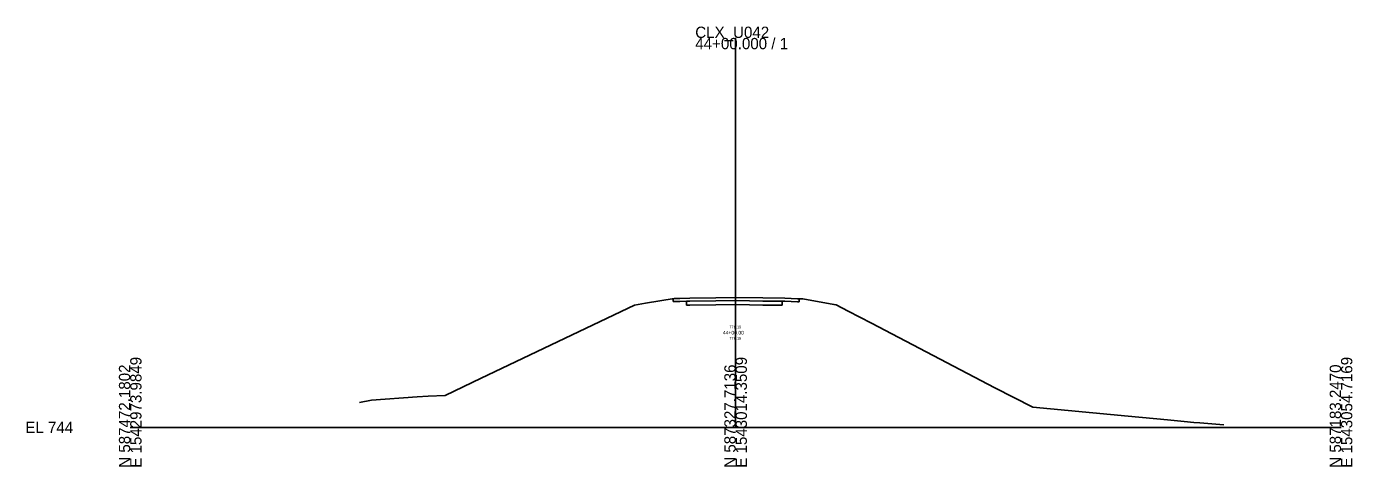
# Model space of a CAD drawing. Extents: x -26 to 1603, y -10 to 5557.
# Drawn here: x -25.7 to 302.8, y -9.7 to 99.4 of the extents above; entities that cross this region are included whole.
import ezdxf

# ---------------------------------------------------------------- set-up
doc = ezdxf.new("R2010")
doc.units = 0
for name, color, linetype in [('GK_Cells', 7, 'Continuous'), ('XS_P_Annotation', 7, 'Continuous'), ('XS_X_Ground_Line', 7, 'Continuous'), ('XS_X_Pavt', 7, 'Continuous')]:
    doc.layers.add(name, color=color, linetype=linetype)

msp = doc.modelspace()

# ---------------------------------------------------------------- linework, layer by layer
at = {"layer": 'GK_Cells'}
for p, q in [((150, 0), (150, 96.59)), ((0, 0), (150, 0)), ((150, 0), (300, 0))]:
    msp.add_line(p, q, dxfattribs=at)
at = {"layer": 'XS_X_Ground_Line'}
msp.add_lwpolyline([(56.77, 6.22), (59.82, 6.79), (71.1, 7.56), (73.84, 7.71), (78.06, 7.94), (86.95, 12.19), (124.92, 30.34), (127.66, 30.79), (134.8, 31.99), (136.21, 32.01), (138.62, 32.05), (145.12, 32.13), (150.17, 32.2), (156.78, 32.1), (162.18, 32.02), (165.32, 31.92), (166.62, 31.88), (174.37, 30.5), (174.95, 30.39), (177.91, 28.84), (183.69, 25.82), (214.25, 9.83), (223.62, 4.99), (247.29, 2.77), (256.98, 1.87), (261.17, 1.48), (263.51, 1.26), (265.01, 1.12), (270.98, 0.63)], dxfattribs=at)
at = {"layer": 'XS_X_Pavt'}
for p, q in [((134.5, 31.94), (134.5, 31.19)), ((134.5, 31.19), (134.8, 31.24)), ((134.8, 31.24), (136.21, 31.26)), ((136.21, 31.26), (137.87, 31.29)), ((137.87, 31.29), (138.62, 31.3)), ((137.87, 31.29), (137.87, 30.29)), ((137.87, 30.29), (138.62, 30.3)), ((138.62, 31.3), (145.12, 31.38)), ((138.62, 30.3), (145.12, 30.38)), ((145.12, 31.38), (150.17, 31.45)), ((145.12, 30.38), (150.17, 30.45)), ((150.17, 31.45), (156.78, 31.35)), ((150.17, 30.45), (156.78, 30.35)), ((156.78, 31.35), (161.52, 31.28)), ((156.78, 30.35), (161.52, 30.28)), ((161.52, 31.28), (162.18, 31.27)), ((161.52, 31.28), (161.52, 30.28)), ((162.18, 31.27), (165.32, 31.17)), ((165.32, 31.17), (165.72, 31.16)), ((165.72, 31.91), (165.72, 31.16))]:
    msp.add_line(p, q, dxfattribs=at)

# ---------------------------------------------------------------- texts
at = {"layer": 'GK_Cells'}
for s, p in [('CLX_U042', (140, 96.59)), ('44+00.000 / 1', (140, 93.79)), ('EL 744', (-26, -1.4))]:
    msp.add_text(s, height=2.8, dxfattribs=at).set_placement(p)
for s, p in [('E 1542973.9849', (2.8, -10)), ('E 1543014.3509', (152.8, -10)), ('E 1543054.7169', (302.8, -10)), ('N 587472.1802', (0, -10)), ('N 587327.7136', (150, -10)), ('N 587183.2470', (300, -10))]:
    msp.add_text(s, height=2.8, rotation=90, dxfattribs=at).set_placement(p)
at = {"layer": 'XS_P_Annotation'}
for s, height, p in [('44+00.00', 0.9, (146.84, 23.05)), ('776.19', 0.7, (148.44, 24.55)), ('776.19', 0.7, (148.44, 21.75))]:
    msp.add_text(s, height=height, dxfattribs=at).set_placement(p)

doc.saveas('drawing.dxf')
